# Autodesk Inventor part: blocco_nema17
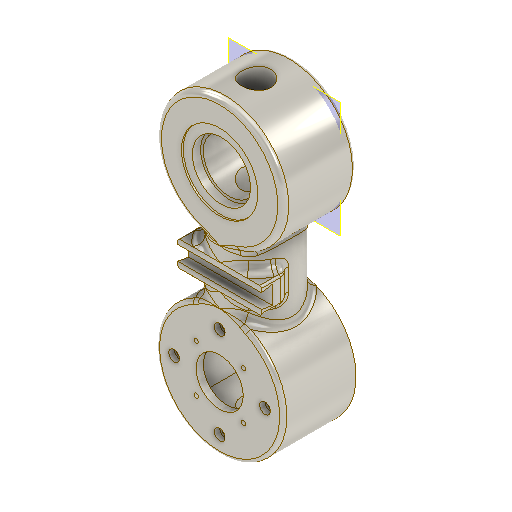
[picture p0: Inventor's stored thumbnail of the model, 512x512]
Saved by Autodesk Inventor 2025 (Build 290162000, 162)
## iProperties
Created: 2025-05
Part Number: blocco_nema17
Material: Titanio
Document SubType Name: Modeling
Designer: 18907419
Density: 4.51 g/cm^3
Appearance: Titanio
alezza: 50,000 mm
Author: 18907419
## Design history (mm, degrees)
sketch "Schizzo1"
  geometry: C1 r 35 at (0, 0); 1 further point
  constraints: 1 centre point, 1 coincident
  dimensions: "d0" = 70 diameter of C1
extrude "Estrusione1" new body sketch "Schizzo1" stored distance "d1" = 40; taper "d2" = 0 deg
sketch "Schizzo2"
  geometry: L1 (-35, -20)-(35, -20) reference; L2 (35, 20)-(-35, 20) reference; L3 (35, -20)-(35, 20) reference; L4 (-35, -20)-(-35, 20) reference; C1 r 20 at (0, 0); 1 further point
  constraints: 1 centre point, 1 coincident
  dimensions: "d52" = 40 diameter of C1
extrude "Estrusione2" join sketch "Schizzo2" taper "d4" = 0 deg
sketch "Schizzo7"
  geometry: C1 r 8 at (0, 0); 1 further point
  constraints: 1 centre point, 1 coincident
  dimensions: "d19" = 16 diameter of C1
extrude "Estrusione7" cut sketch "Schizzo7" distance "d20" = 95.5; taper "d21" = 0 deg
sketch "Schizzo12"
  geometry: L1 (-21.05, 21.05)-(21.05, 21.05); L2 (21.05, 21.05)-(21.05, -21.05); L3 (21.05, -21.05)-(-21.05, -21.05); L4 (-21.05, -21.05)-(-21.05, 21.05); L5 (-21.05, 21.05)-(21.05, -21.05); L6 (21.05, 21.05)-(-21.05, -21.05); 1 further point
  constraints: 12 end point, 2 midpoint, 2 parallel, 1 horizontal, 1 perpendicular
  dimensions: "d38" = 42.1 distance of L2.end L3.end; "d39" = 42.1 distance of L1.end L2.end
extrude "Estrusione11" cut sketch "Schizzo12" distance "d40" = 60; taper "d41" = 0 deg
mirror "Speculare2"
sketch "Schizzo13"
  geometry: C1 r 16 at (0, 0); 1 further point
  constraints: 1 centre point
  dimensions: "d42" = 32 diameter of C1
extrude "Estrusione12" cut sketch "Schizzo13" extent not by distance; stored distance "d43" = 32; taper "d44" = 0 deg
mirror "Speculare3"
sketch "Schizzo18"
  geometry: L1 (-21.05, -21.05)-(-21.05, 21.05) reference; L2 (-21.05, 21.05)-(21.05, 21.05) reference; L3 (21.05, 21.05)-(21.05, -21.05) reference; L4 (21.05, -21.05)-(-21.05, -21.05) reference; C1 r 13 at (0, 0); C2 r 1.23 at (13.1, 13.1) reference; C3 r 1.23 at (13.1, -12.9) reference; C4 r 1.23 at (-12.9, -12.9) reference; C5 r 1.23 at (-12.9, 13.1) reference; 3 further points
  constraints: 1 centre point, 1 coincident, 1 vertical alignment
  dimensions: "d63" = 26 diameter of C1
  node "Linea chiusa proiettata5"
  node "Riferimento1"
  node "Riferimento2"
  node "Riferimento3"
  node "Riferimento4"
node "Piano di lavoro2"
extrude "Estrusione16" join sketch "Schizzo18" stored distance "d64" = 3; taper "d65" = 0 deg
sketch "Schizzo19"
  geometry: C1 r 1.7 at (0, 25) reference; 1 further point
hole "Foro3" sketch "Schizzo19" at (0, 25) diameter "d66" = 3.4; stored, may be unused: countersink angle "d70" = 90 deg, drill point angle "d72" = 118 deg; dims "d67" = 6, "d68" = 6.3, "d69" = 3.4, "d71" = 8
sketch "Schizzo20"
  geometry: C1 r 1.7 at (0, 25) reference; 2 further points
  constraints: 1 coincident
hole "Foro4" sketch "Schizzo20" at (0, 25) diameter "d76" = 3.4; stored, may be unused: countersink angle "d80" = 90 deg, drill point angle "d82" = 118 deg; dims "d77" = 6, "d78" = 6, "d79" = 3, "d81" = 8
pattern_circular "Serie circolare2" dims "d84" = 360 deg
fillet "Raccordo2" dims "d88" = 3
fillet "Raccordo3" dims "d89" = 5
fillet "Raccordo4" dims "d90" = 2
fillet "Raccordo5" dims "d91" = 2
node "Piano di lavoro3"
sketch "Schizzo23"
  geometry: L1 (0, 0)-(0, 100); L2 (20, 31.225)-(20, 68.775) reference; L3 (-23, 57)-(23, 57); L4 (23, 57)-(23, 43); L5 (23, 43)-(-23, 43); L6 (-23, 43)-(-23, 57); L7 (-23, 57)-(23, 43); L8 (23, 57)-(-23, 43); C1 r 10.7 at (0, 0) reference; C2 r 16 at (0, 100) reference; 2 further points
  constraints: 14 end point, 3 midpoint, 2 parallel, 1 coincident, 1 horizontal, 1 perpendicular, 1 vertical
  dimensions: "d104" = 46 distance of L4.end L5.end; "d105" = 14 distance of L3.end L4.end
extrude "Estrusione19" join sketch "Schizzo23" distance "d99" = 7; taper "d101" = 0 deg; dims "d100" = 6, "d102" = 0
fillet "Raccordo6" dims "d106" = 5
fillet "Raccordo7" dims "d107" = 5
sketch "Schizzo24"
  geometry: L1 (-10.38, 0)-(-10.38, 14) reference; L2 (-10.38, 0)-(0, 0) reference; L3 (0, 14)-(0, 0) reference; L4 (-10.38, 14)-(0, 14) reference; L5 (0, 7)-(-10.38, 7); L6 (0, 11)-(-6, 12.058); L7 (-6, 12.058)-(-6, 7); L8 (0, 3)-(-6, 1.942); L9 (-6, 1.942)-(-6, 7); L10 (0, 14)-(0, 0) reference; 3 further points
  constraints: 10 end point, 3 midpoint, 2 point on line, 2 symmetric about line, 1 perpendicular
  dimensions: "d108" = 6 distance between parallel lines of L7 L3; "d109" = 80 deg angle of L7 L6; "d113" = 4 distance of point (0, 7) L6.start
extrude "Estrusione20" cut sketch "Schizzo24" extent not by distance; stored distance "d110" = 0; taper "d111" = 0 deg
node "Piano di lavoro4"
sketch "Schizzo25"
  geometry: C1 r 14.5 at (0, 0); C2 r 16 at (0, 0) reference; 1 further point
  constraints: 1 centre point
  dimensions: "d115" = 29 diameter of C1
extrude "Estrusione21" join sketch "Schizzo25" distance "d116" = 30; taper "d117" = 0 deg
sketch "Schizzo26"
  geometry: C1 r 21 at (0, 0); 1 further point
  constraints: 1 centre point
  dimensions: "d118" = 42 diameter of C1
extrude "Estrusione22" cut sketch "Schizzo26" distance "d119" = 1; taper "d120" = 0 deg
fillet "Raccordo9" dims "d121" = 1
fillet "Raccordo10" dims "d122" = 5
sketch "Schizzo27"
  geometry: C1 r 8 at (21.05, 20) reference; C2 r 8 at (21.05, 20); 1 further point
  constraints: 1 centre point, 1 coincident, 1 concentric
extrude "Estrusione23" cut sketch "Schizzo27" extent not by distance; stored distance "d123" = 0; taper "d124" = 0 deg
node "Solido1"
node "Linea chiusa proiettata1"
node "Riferimento5"
node "Riferimento7"
node "Linea chiusa proiettata7"
other parameters: "d92" = 13, "d114" = -4.5
